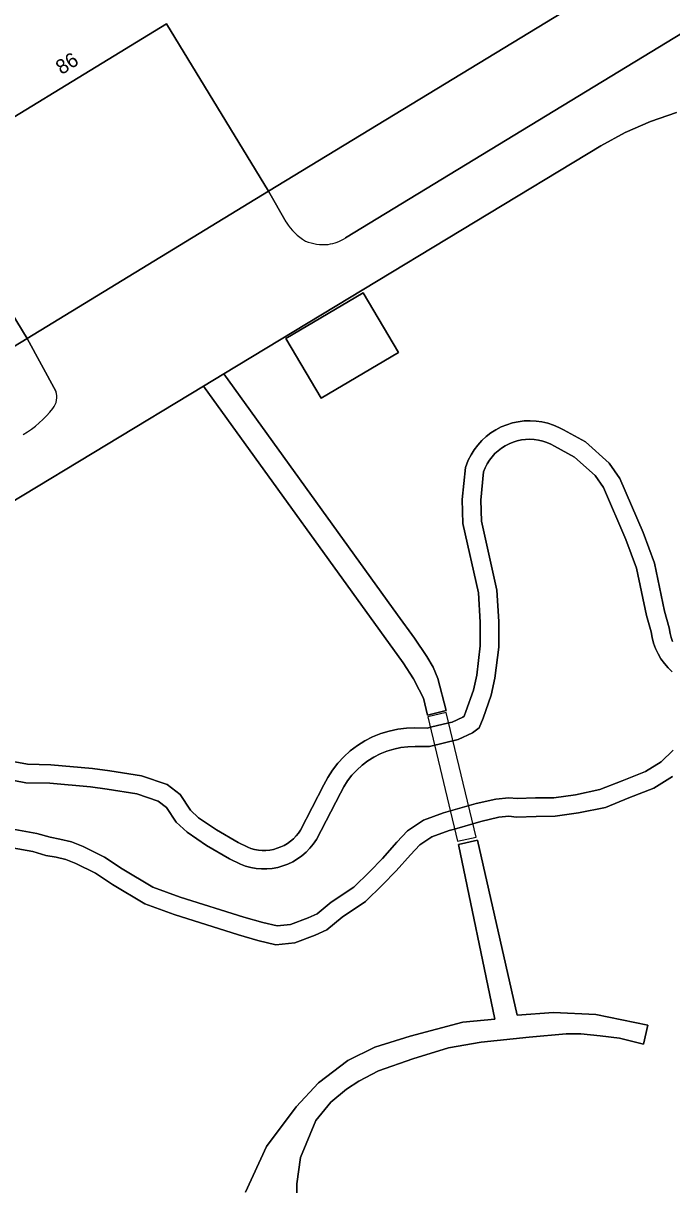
# Model space of a CAD drawing. Extents: x 158132 to 159664, y 385256 to 387218.
# Drawn here: x 158472.6 to 158517.1, y 386648.1 to 386727.8 of the extents above; entities that cross this region are included whole.
import ezdxf

# ---------------------------------------------------------------- set-up
doc = ezdxf.new("R2010")
doc.units = 0
for name, color, linetype in [('IMGEO_Dek', 7, 'Continuous'), ('IMGEO_Groenvoorziening', 7, 'Continuous'), ('IMGEO_Meer_plas_ven_vijver', 7, 'Continuous'), ('IMGEO_Oever', 7, 'Continuous'), ('IMGEO_Pand', 7, 'Continuous'), ('IMGEO_Pand_nummerreeks', 7, 'Continuous'), ('IMGEO_Rijbaan_lokaal_gesloten', 7, 'Continuous'), ('IMGEO_Voetpad_gesloten', 7, 'Continuous'), ('IMGEO_Voetpad_onverhard', 7, 'Continuous'), ('IMGEO_Voetpad_open', 7, 'Continuous')]:
    doc.layers.add(name, color=color, linetype=linetype)

msp = doc.modelspace()

# ---------------------------------------------------------------- linework, layer by layer
at = {"layer": 'IMGEO_Dek'}
msp.add_lwpolyline([(158503.684, 386671.973), (158501.643, 386680.523), (158500.385, 386680.224), (158502.402, 386671.703)], close=True, dxfattribs=at)
at = {"layer": 'IMGEO_Groenvoorziening'}
for points in [[(158494.739, 386713.107), (158549.847, 386746.679), (158551.238, 386747.502), (158552.376, 386748.512), (158553.732, 386750.16), (158554.526, 386751.144), (158554.922, 386751.924), (158555.829, 386753.423), (158555.906, 386753.622), (158555.703, 386756.791), (158555.583, 386757.514), (158554.793, 386760.514), (158552.838, 386765.802), (158547.628, 386781.441), (158549.963, 386782.629), (158547.791, 386786.1), (158556.865, 386791.465), (158557.718, 386792.053), (158556.9, 386794.277)], [(158474.849, 386702.587), (158472.879, 386706.215), (158420.093, 386674.064), (158404.591, 386699.515), (158523.53, 386771.958), (158539.032, 386746.507), (158489.447, 386716.307), (158490.659, 386714.179)], [(158517.449, 386721.711), (158515.651, 386721.097), (158513.91, 386720.335), (158512.239, 386719.43), (158486.387, 386703.781), (158498.301, 386687.229), (158499.467, 386685.622), (158500.314, 386684.386), (158500.748, 386683.651), (158501.058, 386682.857), (158501.642, 386680.672), (158500.355, 386680.354), (158500.069, 386681.511), (158499.783, 386682.084), (158499.399, 386682.836), (158498.674, 386683.951), (158484.978, 386702.928), (158471.675, 386694.875)], [(158471.177, 386677.301), (158472.919, 386676.98), (158474.502, 386676.948), (158477.378, 386676.688), (158478.553, 386676.531), (158480.724, 386676.191), (158482.49, 386675.582), (158483.38, 386674.892), (158484.083, 386673.833), (158484.651, 386673.301), (158485.876, 386672.476), (158487.374, 386671.601), (158488.016, 386671.276), (158488.241, 386671.195), (158488.494, 386671.129), (158488.752, 386671.084), (158489.011, 386671.063), (158489.271, 386671.065), (158489.531, 386671.089), (158489.789, 386671.137), (158490.04, 386671.207), (158490.284, 386671.298), (158490.52, 386671.411), (158490.743, 386671.543), (158490.956, 386671.697), (158491.155, 386671.867), (158491.336, 386672.053), (158491.5, 386672.255), (158491.636, 386672.456), (158493.248, 386675.57), (158493.505, 386676.058), (158493.831, 386676.566), (158494.201, 386677.044), (158494.611, 386677.486), (158495.058, 386677.892), (158495.541, 386678.257), (158496.053, 386678.577), (158496.591, 386678.852), (158497.15, 386679.078), (158497.727, 386679.254), (158498.318, 386679.38), (158498.918, 386679.452), (158499.492, 386679.471), (158500.347, 386679.464), (158500.553, 386679.513), (158501.811, 386679.817), (158502.044, 386679.874), (158502.77, 386680.216), (158502.863, 386680.286), (158502.993, 386680.592), (158503.508, 386682.062), (158503.732, 386683.1), (158503.973, 386685.098), (158503.976, 386686.725), (158503.843, 386688.746), (158502.784, 386693.506), (158502.742, 386695.152), (158502.952, 386697.36), (158503.154, 386697.86), (158503.342, 386698.226), (158503.559, 386698.569), (158503.805, 386698.893), (158504.081, 386699.197), (158504.382, 386699.473), (158504.706, 386699.723), (158505.05, 386699.942), (158505.412, 386700.13), (158505.791, 386700.286), (158506.181, 386700.408), (158506.581, 386700.494), (158506.984, 386700.545), (158507.391, 386700.562), (158507.803, 386700.541), (158508.206, 386700.483), (158508.603, 386700.393), (158508.995, 386700.265), (158509.369, 386700.104), (158509.686, 386699.935), (158511.187, 386699.107), (158512.822, 386697.653), (158513.548, 386696.586), (158515.151, 386692.883), (158515.928, 386690.791), (158516.612, 386687.495), (158516.93, 386686.345), (158517.001, 386685.955), (158517.076, 386685.68), (158517.175, 386685.414)], [(158517.163, 386676.134), (158515.886, 386675.34), (158514.171, 386674.665), (158512.558, 386674.019), (158510.716, 386673.634), (158509.114, 386673.416), (158507.805, 386673.398), (158506.466, 386673.355), (158505.939, 386673.407), (158505.256, 386673.335), (158504.007, 386673.049), (158503.464, 386672.893), (158502.206, 386672.53), (158501.839, 386672.424), (158500.663, 386672.004), (158499.817, 386671.438), (158499.185, 386670.77), (158498.196, 386669.651), (158497.265, 386668.701), (158496.11, 386667.562), (158494.502, 386666.49), (158493.45, 386665.611), (158492.641, 386665.255), (158491.25, 386664.722), (158489.951, 386664.592), (158488.724, 386664.884), (158487.394, 386665.269), (158482.967, 386666.661), (158480.967, 386667.391), (158478.733, 386668.733), (158477.566, 386669.507), (158476.216, 386670.166), (158475.538, 386670.433), (158474.867, 386670.601), (158474.165, 386670.725), (158473.271, 386670.985), (158471.849, 386671.238)], [(158487.862, 386647.614), (158489.298, 386650.749), (158491.346, 386653.462), (158492.882, 386655.116), (158494.894, 386656.635), (158496.747, 386657.552), (158499.159, 386658.314), (158502.775, 386659.264), (158504.974, 386659.482), (158502.477, 386671.463), (158503.793, 386671.769), (158506.498, 386659.745), (158508.993, 386659.939), (158511.909, 386659.795), (158515.465, 386659.059), (158515.186, 386657.755), (158513.518, 386658.181), (158512.206, 386658.324), (158510.878, 386658.472), (158509.868, 386658.465), (158507.326, 386658.246), (158504.042, 386657.902), (158501.8, 386657.519), (158499.352, 386656.746), (158497.001, 386655.931), (158495.642, 386655.216), (158494.799, 386654.685), (158493.718, 386653.77), (158492.703, 386652.532), (158491.64, 386649.986), (158491.386, 386648.172), (158491.391, 386647.125)]]:
    msp.add_lwpolyline(points, dxfattribs=at)
msp.add_lwpolyline([(158490.634, 386706.209), (158495.938, 386709.34), (158498.362, 386705.232), (158493.059, 386702.101)], close=True, dxfattribs=at)
for centre, radius, start, end in [((158494.117, 386716.402), 4.111, 212.73221, 238.75591), ((158493.202, 386715.898), 3.248, 247.99319, 275.97364), ((158493.089, 386715.758), 3.123, 278.31302, 301.90623), ((158473.735, 386702.176), 1.187, 319.71392, 20.27566), ((158469.246, 386705.461), 6.748, 299.96112, 323.0843)]:
    msp.add_arc(centre, radius, start, end, dxfattribs=at)
at = {"layer": 'IMGEO_Meer_plas_ven_vijver'}
for points in [[(158517.145, 386683.32), (158516.863, 386683.598), (158516.606, 386683.898), (158516.376, 386684.221), (158516.175, 386684.562), (158516.005, 386684.919), (158515.867, 386685.29), (158515.762, 386685.672), (158515.691, 386686.061), (158515.377, 386687.197), (158514.705, 386690.439), (158513.973, 386692.409), (158512.431, 386695.971), (158511.861, 386696.809), (158510.45, 386698.064), (158509.08, 386698.819), (158508.818, 386698.959), (158508.546, 386699.076), (158508.264, 386699.168), (158507.975, 386699.234), (158507.681, 386699.276), (158507.385, 386699.291), (158507.089, 386699.279), (158506.795, 386699.242), (158506.505, 386699.179), (158506.222, 386699.091), (158505.948, 386698.978), (158505.685, 386698.841), (158505.435, 386698.682), (158505.2, 386698.501), (158504.982, 386698.301), (158504.782, 386698.081), (158504.603, 386697.845), (158504.445, 386697.595), (158504.309, 386697.331), (158504.198, 386697.056), (158504.013, 386695.108), (158504.05, 386693.661), (158505.103, 386688.927), (158505.246, 386686.766), (158505.242, 386685.02), (158504.985, 386682.89), (158504.732, 386681.717), (158504.177, 386680.133), (158503.899, 386679.479), (158503.431, 386679.124), (158502.468, 386678.67), (158500.493, 386678.193), (158499.507, 386678.201), (158499.015, 386678.185), (158498.526, 386678.126), (158498.045, 386678.024), (158497.574, 386677.88), (158497.118, 386677.696), (158496.679, 386677.472), (158496.262, 386677.211), (158495.869, 386676.914), (158495.505, 386676.583), (158495.17, 386676.222), (158494.869, 386675.833), (158494.603, 386675.419), (158494.374, 386674.983), (158492.729, 386671.806), (158492.52, 386671.497), (158492.285, 386671.208), (158492.025, 386670.941), (158491.742, 386670.698), (158491.439, 386670.48), (158491.119, 386670.29), (158490.782, 386670.129), (158490.433, 386669.998), (158490.074, 386669.899), (158489.707, 386669.831), (158489.336, 386669.796), (158488.963, 386669.793), (158488.592, 386669.824), (158488.224, 386669.887), (158487.864, 386669.982), (158487.513, 386670.108), (158486.767, 386670.485), (158485.201, 386671.4), (158483.857, 386672.305), (158483.107, 386673.008), (158482.438, 386674.016), (158481.878, 386674.45), (158480.416, 386674.954), (158478.371, 386675.275), (158477.237, 386675.426), (158474.432, 386675.68), (158472.79, 386675.713), (158471.032, 386676.037)], [(158472.035, 386672.494), (158473.56, 386672.223), (158474.454, 386671.963), (158475.132, 386671.843), (158475.926, 386671.645), (158476.728, 386671.329), (158478.198, 386670.611), (158479.411, 386669.807), (158481.517, 386668.542), (158483.375, 386667.863), (158487.761, 386666.484), (158489.048, 386666.112), (158490.037, 386665.876), (158490.954, 386665.968), (158492.158, 386666.429), (158492.774, 386666.7), (158493.741, 386667.508), (158495.305, 386668.551), (158496.366, 386669.597), (158497.267, 386670.516), (158498.248, 386671.626), (158498.992, 386672.414), (158500.088, 386673.147), (158501.449, 386673.633), (158503.69, 386674.279), (158505.047, 386674.589), (158505.935, 386674.683), (158506.508, 386674.626), (158507.776, 386674.667), (158509.019, 386674.684), (158510.5, 386674.886), (158512.189, 386675.239), (158513.703, 386675.845), (158515.314, 386676.479), (158516.381, 386677.142), (158517.214, 386677.94)]]:
    msp.add_lwpolyline(points, dxfattribs=at)
at = {"layer": 'IMGEO_Oever'}
for points in [[(158517.175, 386685.414), (158517.076, 386685.68), (158517.001, 386685.955), (158516.93, 386686.345), (158516.612, 386687.495), (158515.928, 386690.791), (158515.151, 386692.883), (158513.548, 386696.586), (158512.822, 386697.653), (158511.187, 386699.107), (158509.686, 386699.935), (158509.369, 386700.104), (158508.995, 386700.265), (158508.603, 386700.393), (158508.206, 386700.483), (158507.803, 386700.541), (158507.391, 386700.562), (158506.984, 386700.545), (158506.581, 386700.494), (158506.181, 386700.408), (158505.791, 386700.286), (158505.412, 386700.13), (158505.05, 386699.942), (158504.706, 386699.723), (158504.382, 386699.473), (158504.081, 386699.197), (158503.805, 386698.893), (158503.559, 386698.569), (158503.342, 386698.226), (158503.154, 386697.86), (158502.952, 386697.36), (158502.742, 386695.152), (158502.784, 386693.506), (158503.843, 386688.746), (158503.976, 386686.725), (158503.973, 386685.098), (158503.732, 386683.1), (158503.508, 386682.062), (158502.993, 386680.592), (158502.863, 386680.286), (158502.77, 386680.216), (158502.044, 386679.874), (158501.811, 386679.817), (158500.553, 386679.513), (158500.347, 386679.464), (158499.492, 386679.471), (158498.918, 386679.452), (158498.318, 386679.38), (158497.727, 386679.254), (158497.15, 386679.078), (158496.591, 386678.852), (158496.053, 386678.577), (158495.541, 386678.257), (158495.058, 386677.892), (158494.611, 386677.486), (158494.201, 386677.044), (158493.831, 386676.566), (158493.505, 386676.058), (158493.248, 386675.57), (158491.636, 386672.456), (158491.5, 386672.255), (158491.336, 386672.053), (158491.155, 386671.867), (158490.956, 386671.697), (158490.743, 386671.543), (158490.52, 386671.411), (158490.284, 386671.298), (158490.04, 386671.207), (158489.789, 386671.137), (158489.531, 386671.089), (158489.271, 386671.065), (158489.011, 386671.063), (158488.752, 386671.084), (158488.494, 386671.129), (158488.241, 386671.195), (158488.016, 386671.276), (158487.374, 386671.601), (158485.876, 386672.476), (158484.651, 386673.301), (158484.083, 386673.833), (158483.38, 386674.892), (158482.49, 386675.582), (158480.724, 386676.191), (158478.553, 386676.531), (158477.378, 386676.688), (158474.502, 386676.948), (158472.919, 386676.98), (158471.177, 386677.301)], [(158471.032, 386676.037), (158472.79, 386675.713), (158474.432, 386675.68), (158477.237, 386675.426), (158478.371, 386675.275), (158480.416, 386674.954), (158481.878, 386674.45), (158482.438, 386674.016), (158483.107, 386673.008), (158483.857, 386672.305), (158485.201, 386671.4), (158486.767, 386670.485), (158487.513, 386670.108), (158487.864, 386669.982), (158488.224, 386669.887), (158488.592, 386669.824), (158488.963, 386669.793), (158489.336, 386669.796), (158489.707, 386669.831), (158490.074, 386669.899), (158490.433, 386669.998), (158490.782, 386670.129), (158491.119, 386670.29), (158491.439, 386670.48), (158491.742, 386670.698), (158492.025, 386670.941), (158492.285, 386671.208), (158492.52, 386671.497), (158492.729, 386671.806), (158494.374, 386674.983), (158494.603, 386675.419), (158494.869, 386675.833), (158495.17, 386676.222), (158495.505, 386676.583), (158495.869, 386676.914), (158496.262, 386677.211), (158496.679, 386677.472), (158497.118, 386677.696), (158497.574, 386677.88), (158498.045, 386678.024), (158498.526, 386678.126), (158499.015, 386678.185), (158499.507, 386678.201), (158500.493, 386678.193), (158502.468, 386678.67), (158503.431, 386679.124), (158503.899, 386679.479), (158504.177, 386680.133), (158504.732, 386681.717), (158504.985, 386682.89), (158505.242, 386685.02), (158505.246, 386686.766), (158505.103, 386688.927), (158504.05, 386693.661), (158504.013, 386695.108), (158504.198, 386697.056), (158504.309, 386697.331), (158504.445, 386697.595), (158504.603, 386697.845), (158504.782, 386698.081), (158504.982, 386698.301), (158505.2, 386698.501), (158505.435, 386698.682), (158505.685, 386698.841), (158505.948, 386698.978), (158506.222, 386699.091), (158506.505, 386699.179), (158506.795, 386699.242), (158507.089, 386699.279), (158507.385, 386699.291), (158507.681, 386699.276), (158507.975, 386699.234), (158508.264, 386699.168), (158508.546, 386699.076), (158508.818, 386698.959), (158509.08, 386698.819), (158510.45, 386698.064), (158511.861, 386696.809), (158512.431, 386695.971), (158513.973, 386692.409), (158514.705, 386690.439), (158515.377, 386687.197), (158515.691, 386686.061), (158515.762, 386685.672), (158515.867, 386685.29), (158516.005, 386684.919), (158516.175, 386684.562), (158516.376, 386684.221), (158516.606, 386683.898), (158516.863, 386683.598), (158517.145, 386683.32)], [(158517.214, 386677.94), (158516.381, 386677.142), (158515.314, 386676.479), (158513.703, 386675.845), (158512.189, 386675.239), (158510.5, 386674.886), (158509.019, 386674.684), (158507.776, 386674.667), (158506.508, 386674.626), (158505.935, 386674.683), (158505.047, 386674.589), (158503.69, 386674.279), (158501.449, 386673.633), (158500.088, 386673.147), (158498.992, 386672.414), (158498.248, 386671.626), (158497.267, 386670.516), (158496.366, 386669.597), (158495.305, 386668.551), (158493.741, 386667.508), (158492.774, 386666.7), (158492.158, 386666.429), (158490.954, 386665.968), (158490.037, 386665.876), (158489.048, 386666.112), (158487.761, 386666.484), (158483.375, 386667.863), (158481.517, 386668.542), (158479.411, 386669.807), (158478.198, 386670.611), (158476.728, 386671.329), (158475.926, 386671.645), (158475.132, 386671.843), (158474.454, 386671.963), (158473.56, 386672.223), (158472.035, 386672.494)], [(158471.849, 386671.238), (158473.271, 386670.985), (158474.165, 386670.725), (158474.867, 386670.601), (158475.538, 386670.433), (158476.216, 386670.166), (158477.566, 386669.507), (158478.733, 386668.733), (158480.967, 386667.391), (158482.967, 386666.661), (158487.394, 386665.269), (158488.724, 386664.884), (158489.951, 386664.592), (158491.25, 386664.722), (158492.641, 386665.255), (158493.45, 386665.611), (158494.502, 386666.49), (158496.11, 386667.562), (158497.265, 386668.701), (158498.196, 386669.651), (158499.185, 386670.77), (158499.817, 386671.438), (158500.663, 386672.004), (158501.839, 386672.424), (158502.206, 386672.53), (158503.464, 386672.893), (158504.007, 386673.049), (158505.256, 386673.335), (158505.939, 386673.407), (158506.466, 386673.355), (158507.805, 386673.398), (158509.114, 386673.416), (158510.716, 386673.634), (158512.558, 386674.019), (158514.171, 386674.665), (158515.886, 386675.34), (158517.163, 386676.134)]]:
    msp.add_lwpolyline(points, dxfattribs=at)
at = {"layer": 'IMGEO_Pand'}
for points in [[(158472.879, 386706.215), (158465.883, 386717.702), (158482.451, 386727.794), (158489.447, 386716.307), (158539.032, 386746.507), (158523.53, 386771.958), (158404.591, 386699.515), (158420.093, 386674.064)], [(158490.634, 386706.209), (158493.059, 386702.101), (158498.362, 386705.232), (158495.938, 386709.34)]]:
    msp.add_lwpolyline(points, close=True, dxfattribs=at)
at = {"layer": 'IMGEO_Rijbaan_lokaal_gesloten'}
for points in [[(158569.832, 386750.876), (158549.963, 386782.629), (158547.628, 386781.441), (158552.838, 386765.802), (158554.793, 386760.514), (158555.583, 386757.514), (158555.703, 386756.791), (158555.906, 386753.622), (158555.829, 386753.423), (158554.922, 386751.924), (158554.526, 386751.144), (158553.732, 386750.16), (158552.376, 386748.512), (158551.238, 386747.502), (158549.847, 386746.679), (158494.739, 386713.107)], [(158443.511, 386617.236), (158439.91, 386656.204), (158439.503, 386661.778), (158439.459, 386666.389), (158439.534, 386668.847), (158439.821, 386671.153), (158440.046, 386672.161), (158440.359, 386673.144), (158440.759, 386674.096), (158441.242, 386675.009), (158441.805, 386675.874), (158442.442, 386676.686), (158443.149, 386677.439), (158443.921, 386678.125), (158444.75, 386678.739), (158445.631, 386679.278), (158450.156, 386681.913), (158471.675, 386694.875), (158484.978, 386702.928), (158486.387, 386703.781), (158512.239, 386719.43), (158513.91, 386720.335), (158515.651, 386721.097), (158517.449, 386721.711)], [(158490.659, 386714.179), (158489.447, 386716.307), (158472.879, 386706.215), (158474.849, 386702.587)]]:
    msp.add_lwpolyline(points, dxfattribs=at)
for centre, radius, start, end in [((158494.117, 386716.402), 4.111, 212.73221, 238.75591), ((158493.202, 386715.898), 3.248, 247.99319, 275.97364), ((158493.089, 386715.758), 3.123, 278.31302, 301.90623), ((158473.735, 386702.176), 1.187, 319.71392, 20.27566), ((158469.246, 386705.461), 6.748, 299.96112, 323.0843)]:
    msp.add_arc(centre, radius, start, end, dxfattribs=at)
at = {"layer": 'IMGEO_Voetpad_gesloten'}
msp.add_lwpolyline([(158503.684, 386671.973), (158501.643, 386680.523), (158500.385, 386680.224), (158502.402, 386671.703)], close=True, dxfattribs=at)
at = {"layer": 'IMGEO_Voetpad_onverhard'}
msp.add_lwpolyline([(158486.387, 386703.781), (158484.978, 386702.928), (158498.674, 386683.951), (158499.399, 386682.836), (158499.783, 386682.084), (158500.069, 386681.511), (158500.355, 386680.354), (158501.642, 386680.672), (158501.058, 386682.857), (158500.748, 386683.651), (158500.314, 386684.386), (158499.467, 386685.622), (158498.301, 386687.229)], close=True, dxfattribs=at)
msp.add_lwpolyline([(158491.391, 386647.125), (158491.386, 386648.172), (158491.64, 386649.986), (158492.703, 386652.532), (158493.718, 386653.77), (158494.799, 386654.685), (158495.642, 386655.216), (158497.001, 386655.931), (158499.352, 386656.746), (158501.8, 386657.519), (158504.042, 386657.902), (158507.326, 386658.246), (158509.868, 386658.465), (158510.878, 386658.472), (158512.206, 386658.324), (158513.518, 386658.181), (158515.186, 386657.755), (158515.465, 386659.059), (158511.909, 386659.795), (158508.993, 386659.939), (158506.498, 386659.745), (158503.793, 386671.769), (158502.477, 386671.463), (158504.974, 386659.482), (158502.775, 386659.264), (158499.159, 386658.314), (158496.747, 386657.552), (158494.894, 386656.635), (158492.882, 386655.116), (158491.346, 386653.462), (158489.298, 386650.749), (158487.862, 386647.614)], dxfattribs=at)
at = {"layer": 'IMGEO_Voetpad_open'}
msp.add_lwpolyline([(158472.879, 386706.215), (158489.447, 386716.307), (158482.451, 386727.794), (158465.883, 386717.702)], close=True, dxfattribs=at)

# ---------------------------------------------------------------- texts
at = {"layer": 'IMGEO_Pand_nummerreeks'}
msp.add_text('86', height=1, rotation=31.99969, dxfattribs=at).set_placement((158475.244, 386724.28))

doc.saveas('drawing.dxf')
